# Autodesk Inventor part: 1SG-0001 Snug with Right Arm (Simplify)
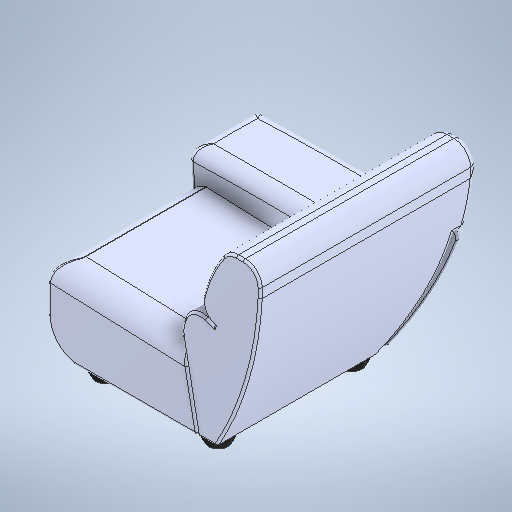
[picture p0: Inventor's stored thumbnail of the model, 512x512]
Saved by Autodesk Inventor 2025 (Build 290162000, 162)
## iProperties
Created: 2025-08
Part Number: 1SG-0001 Snug with Right Arm (Simplify)
Material: Generic
Document SubType Name: Modeling
Designer: Mark.Glazzard
Density: 1 g/cm^3
Appearance: Default
Author: Mark.Glazzard
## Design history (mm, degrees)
derived "1SG-0001 Snug with Right Arm (Simplify) 2022.iam"
body "Solid1"
body "Solid2"
body "Solid3"
body "Solid4"
body "Solid5"
body "Solid6"
body "Solid7"
